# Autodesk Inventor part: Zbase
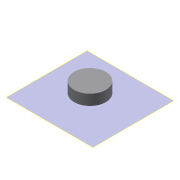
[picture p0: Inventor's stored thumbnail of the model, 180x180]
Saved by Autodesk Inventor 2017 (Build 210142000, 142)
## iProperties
Part Number: Zbase
Material: 一般
Document SubType Name: Modeling
Designer: kyushu-hep
Density: 1 g/cm^3
Appearance: 既定
Author: kyushu-hep
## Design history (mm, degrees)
node "作業平面1"
sketch "スケッチ1"
  geometry: C1 r 30 at (0, 0); 1 further point
  constraints: 1 centre point, 1 coincident
  dimensions: "d0" = 60 diameter of C1
extrude "押し出し1" new body sketch "スケッチ1" distance "d1" = 20; taper "d2" = 0 deg
node "ソリッド1"
